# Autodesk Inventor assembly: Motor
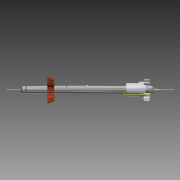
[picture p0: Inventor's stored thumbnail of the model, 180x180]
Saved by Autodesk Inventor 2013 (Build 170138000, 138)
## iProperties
Created: 2008-07
Part Number: Motor
Document SubType Name: Assembly
Designer: tangg
Mass: 130.161 g
Surface Area: 104.869 cm^2
Volume: 19.3028 cm^3
Density: 6.7431 g/cm^3
Author: tangg
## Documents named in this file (4)
- C:\Users\boganb\Documents\B2 Design\Goodyear\2013 Tutorial Files\Dynamic Simulation 1 and 2\Motor.iam
- C:\Users\boganb\Documents\B2 Design\Goodyear\2013 Tutorial Files\Dynamic Simulation 1 and 2\Motor shaft.ipt
- C:\Users\boganb\Documents\B2 Design\Goodyear\2013 Tutorial Files\Dynamic Simulation 1 and 2\Cooling fan.ipt
- C:\Users\boganb\Documents\B2 Design\Goodyear\2013 Tutorial Files\Dynamic Simulation 1 and 2\Bevel Gear11.ipt
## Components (3 placed, 3 different names)
1. Motor shaft:1 — Mate:1, Mate:2, Flush:1
2. Cooling fan:1 — Mate:1
3. Bevel Gear1:1 — Mate:2, Flush:1
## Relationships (3: Mate 2, Flush 1)
- Mate:1: Motor shaft:1 ↔ Cooling fan:1
- Mate:2: Motor shaft:1 ↔ Bevel Gear1:1
- Flush:1: Motor shaft:1 ↔ Bevel Gear1:1
